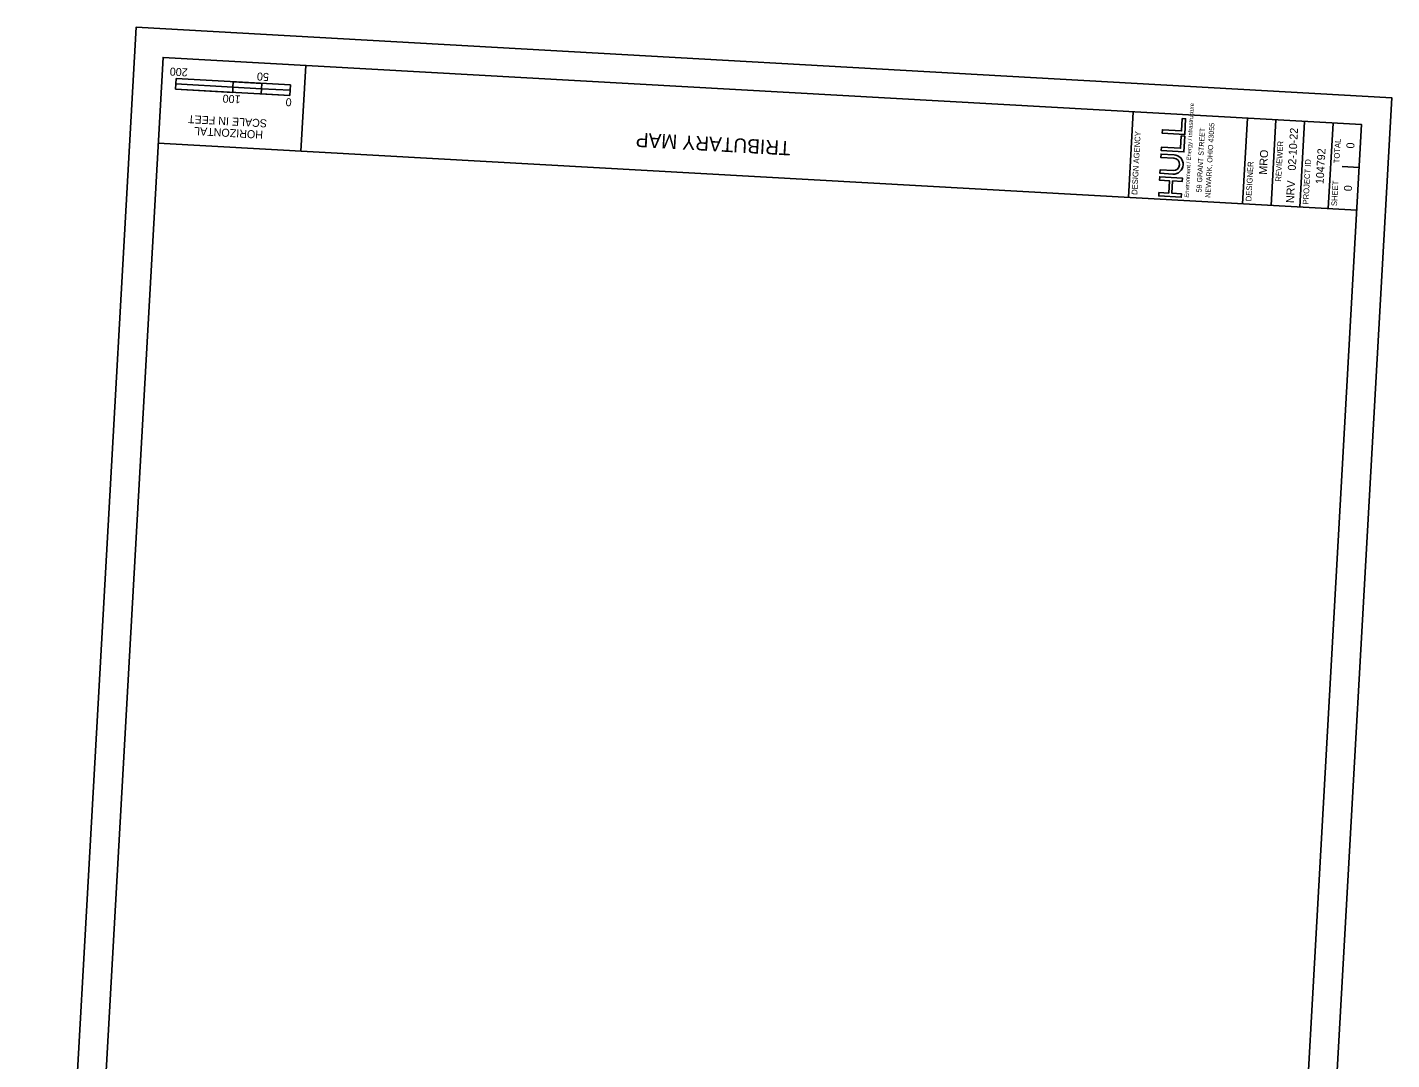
# Model space of a CAD drawing. Extents: x 1969596 to 1974574, y 734795 to 738409.
# Drawn here: x 1972187 to 1974574, y 736602 to 738409 of the extents above; entities that cross this region are included whole.
import ezdxf

# ---------------------------------------------------------------- set-up
doc = ezdxf.new("R2010")
doc.units = 0
for name, color, linetype in [('Default', 7, 'Continuous'), ('DV_X_Setback', 7, 'Continuous'), ('PV_P_Walk', 7, 'Continuous'), ('RS_Raster1', 7, 'Continuous'), ('RW_X_Esmt_General', 7, 'Continuous')]:
    doc.layers.add(name, color=color, linetype=linetype)

msp = doc.modelspace()

# ---------------------------------------------------------------- linework, layer by layer
at = {"layer": 'Default'}
for p, q in [((1974203.5, 738168.1), (1974203.5, 738168.1)), ((1974203.5, 738168.1), (1974203.5, 738168.1)), ((1974209.5, 738167.8), (1974209.5, 738167.8))]:
    msp.add_line(p, q, dxfattribs=at)
for points in [[(1974173.2, 738229.3), (1974172.9, 738223.3), (1974212.5, 738221.1), (1974214, 738248.7), (1974208, 738249), (1974206.8, 738227.5)], [(1974172.9, 738223.3), (1974212.5, 738221.1), (1974214, 738248.7), (1974208, 738249), (1974206.8, 738227.5), (1974173.2, 738229.3)], [(1974171.5, 738198.9), (1974171.2, 738192.9), (1974210.8, 738190.7), (1974212.3, 738218.2), (1974206.3, 738218.6), (1974205.1, 738197)], [(1974171.2, 738192.9), (1974210.8, 738190.7), (1974212.3, 738218.2), (1974206.3, 738218.6), (1974205.1, 738197), (1974171.5, 738198.9)], [(1974168.6, 738147.1), (1974168.3, 738141.1), (1974185.7, 738140.1), (1974184.5, 738118.6), (1974167.1, 738119.6), (1974166.8, 738113.6), (1974206.3, 738111.4), (1974206.7, 738117.4), (1974189.9, 738118.3), (1974191.1, 738139.8), (1974207.9, 738138.9), (1974208.2, 738144.9)]]:
    msp.add_lwpolyline(points, close=True, dxfattribs=at)
for points in [[(1974193.6, 738185.6), (1974170.9, 738186.9), (1974170.5, 738180.9), (1974193.3, 738179.6)], [(1974193.3, 738179.6), (1974170.5, 738180.9), (1974170.9, 738186.9), (1974193.6, 738185.6)], [(1974192, 738157.9), (1974169.3, 738159.2), (1974169, 738153.2), (1974191.7, 738151.9)], [(1974191.7, 738151.9), (1974169, 738153.2), (1974169.3, 738159.2), (1974192, 738157.9)], [(1974168.6, 738147.1), (1974168.6, 738147.1), (1974208.2, 738144.9), (1974207.9, 738138.9), (1974191.1, 738139.8), (1974189.9, 738118.3), (1974206.7, 738117.4), (1974206.3, 738111.4), (1974166.8, 738113.6), (1974167.1, 738119.6), (1974184.5, 738118.6), (1974185.7, 738140.1), (1974168.3, 738141.1), (1974168.6, 738147.1)]]:
    msp.add_lwpolyline(points, dxfattribs=at)
for centre, radius, start, end in [((1974192.7, 738168.8), 10.8, 356.7893, 86.7893), ((1974192.7, 738168.8), 10.8, 356.7893, 86.7893), ((1974192.7, 738168.8), 16.9, 356.745, 86.7893), ((1974192.7, 738168.8), 16.9, 356.7893, 86.7893), ((1974192.6, 738168.7), 16.9, 266.7893, 356.8335), ((1974192.6, 738168.7), 16.9, 266.7893, 356.7893), ((1974192.6, 738168.7), 10.8, 266.7893, 356.7893), ((1974192.6, 738168.7), 10.8, 266.7893, 356.7893)]:
    msp.add_arc(centre, radius, start, end, dxfattribs=at)
at = {"layer": 'DV_X_Setback'}
for p, q in [((1972666.2, 738192.2), (1972674.7, 738342)), ((1974114, 738111), (1974122.4, 738260.8)), ((1974313.7, 738099.8), (1974322.1, 738249.6)), ((1974363.6, 738097), (1974372, 738246.8)), ((1974413.5, 738094.2), (1974421.9, 738244)), ((1974463.4, 738091.4), (1974471.8, 738241.2)), ((1974513.3, 738088.6), (1972416.6, 738206.2))]:
    msp.add_line(p, q, dxfattribs=at)
msp.add_lwpolyline([(1972245.8, 735161), (1972425, 738356), (1974521.7, 738238.4), (1974342.5, 735043.4)], close=True, dxfattribs=at)
at = {"layer": 'RS_Raster1'}
msp.add_lwpolyline([(1974384, 734890.9), (1974574.5, 738285.5), (1972377.9, 738408.7), (1972187.5, 735014.1)], close=True, dxfattribs=at)
at = {"layer": 'RW_X_Esmt_General'}
for p, q in [((1972448, 738319.1), (1972447, 738300.4)), ((1972448, 738319.1), (1972647.7, 738307.9)), ((1972447, 738300.4), (1972447.5, 738309.7)), ((1972646.6, 738289.2), (1972447, 738300.4)), ((1972546.8, 738294.8), (1972447, 738300.4)), ((1972447.5, 738309.8), (1972547.3, 738304.2)), ((1972447.5, 738309.7), (1972447.5, 738309.8)), ((1972547.3, 738304.2), (1972546.8, 738294.8)), ((1972547.8, 738313.4), (1972547.3, 738304.1)), ((1972547.3, 738304.1), (1972597.2, 738301.3)), ((1972597.8, 738310.6), (1972547.8, 738313.4)), ((1972597.2, 738301.3), (1972596.7, 738292)), ((1972596.7, 738292), (1972646.6, 738289.2)), ((1972597.2, 738301.3), (1972597.8, 738310.6)), ((1972647.2, 738298.5), (1972597.2, 738301.3)), ((1972647.7, 738307.9), (1972646.6, 738289.2)), ((1972646.6, 738289.2), (1972647.2, 738298.5)), ((1974218, 738180.3), (1974218, 738180.3)), ((1974517.5, 738163.5), (1974487.6, 738165.2)), ((1974498, 738127), (1974498, 738127))]:
    msp.add_line(p, q, dxfattribs=at)

# ---------------------------------------------------------------- texts
at = {"layer": 'Default'}
msp.add_text('Environment / Energy / Infrastructure ', height=7.349, rotation=86.7893, dxfattribs=at).set_placement((1974219.3, 738110.5))
at = {"layer": 'PV_P_Walk'}
for s, p in [('59 GRANT STREET', (1974241.6, 738119.6)), ('NEWARK, OHIO 43055', (1974257.1, 738110.2))]:
    msp.add_text(s, height=9, rotation=86.7893, dxfattribs=at).set_placement(p)
at = {"layer": 'RW_X_Esmt_General'}
for s, height, rotation, p in [('200', 14, 176.7893, (1972468.4, 738336.6)), ('50', 14, 176.7893, (1972610.5, 738328.6)), ('100', 14, 176.7893, (1972560.9, 738289.3)), ('0', 14, 176.7893, (1972650.3, 738284.3)), ('SCALE IN FEET', 14, 176.7893, (1972607.2, 738247.4)), ('HORIZONTAL', 14, 176.7893, (1972600.2, 738227.5)), ('TRIBUTARY MAP', 25, 176.7893, (1973523.6, 738209.3)), ('DESIGN AGENCY', 10, 86.7893, (1974129.2, 738115.2)), ('02-10-22', 14, 86.7893, (1974406.5, 738157.6)), ('REVIEWER', 10, 86.7893, (1974380.9, 738138.3)), ('TOTAL', 10, 86.7893, (1974482.9, 738170.5)), ('0', 14, 86.7893, (1974508.9, 738196.3)), ('DESIGNER', 10, 86.7893, (1974328.9, 738104)), ('MRO', 14, 86.7893, (1974356.1, 738150.5)), ('PROJECT ID', 10, 86.7893, (1974428.8, 738098.4)), ('104792', 14, 86.7893, (1974455.3, 738134)), ('NRV', 14, 86.7893, (1974403.4, 738100.8)), ('SHEET', 10, 86.7893, (1974478.7, 738095.6)), ('0', 14, 86.7893, (1974504.7, 738121.5))]:
    msp.add_text(s, height=height, rotation=rotation, dxfattribs=at).set_placement(p)

doc.saveas('drawing.dxf')
